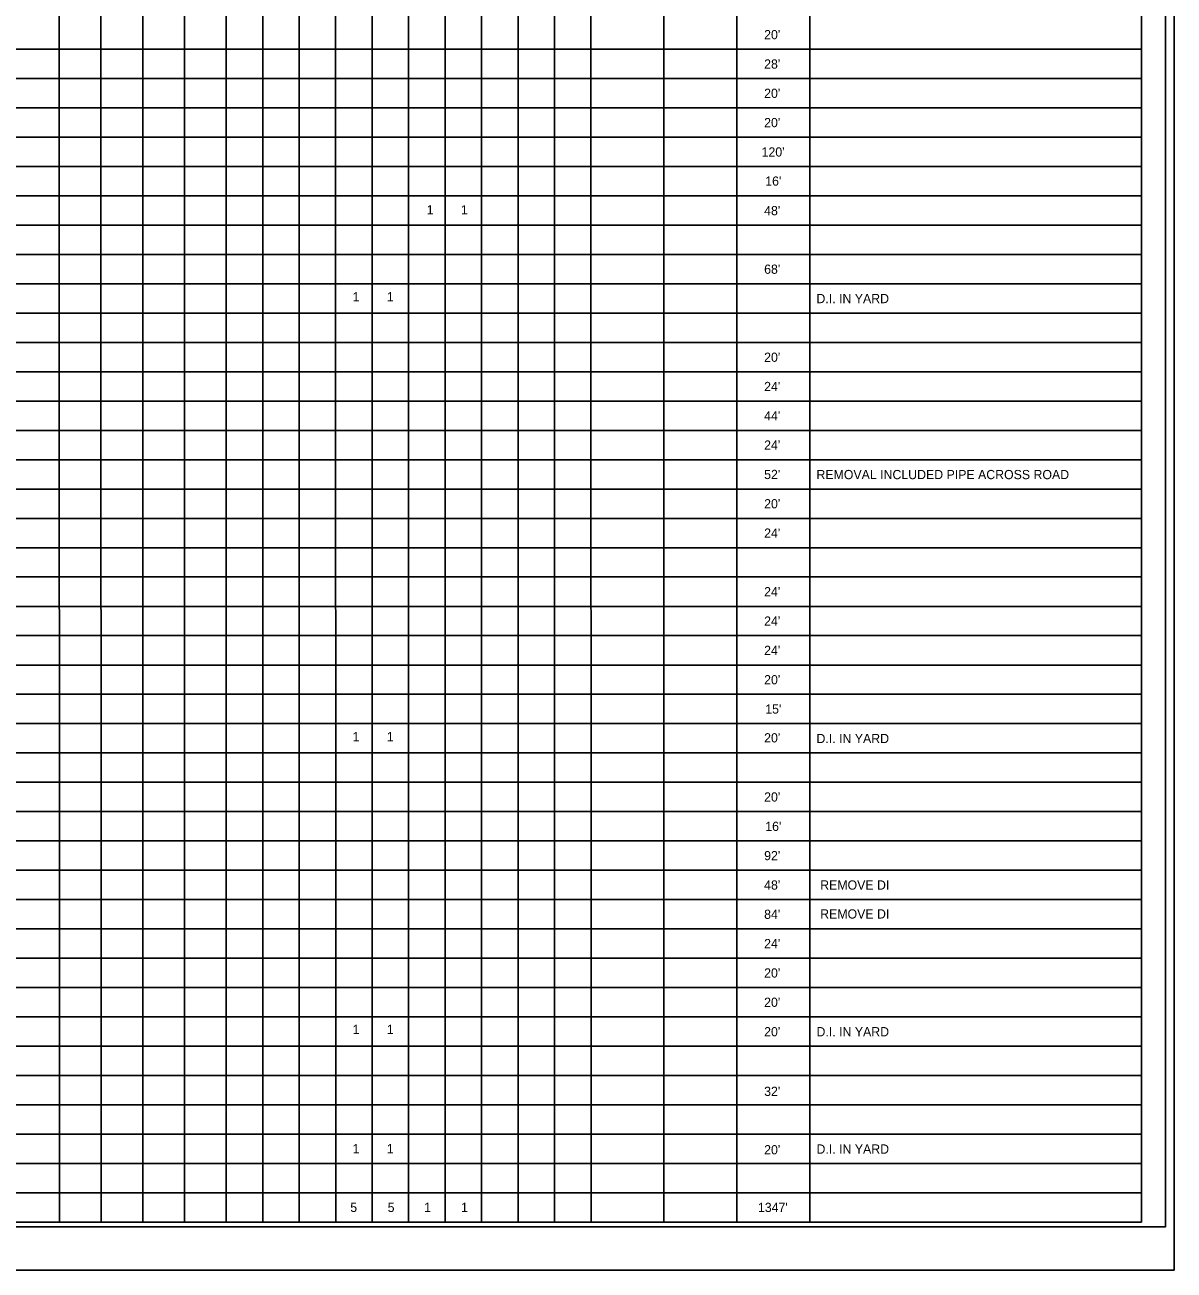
# Model space of a CAD drawing. Extents: x 1912419 to 1914138, y 231793 to 234289.
# Drawn here: x 1913505 to 1914103, y 232988 to 233636 of the extents above; entities that cross this region are included whole.
import ezdxf

# ---------------------------------------------------------------- set-up
doc = ezdxf.new("R2010")
doc.units = 0
for name, color, linetype in [('Sheet Cutting Line CELL', 7, 'Continuous'), ('Sheet Pipe Summary CELL', 7, 'Continuous'), ('Sheet Pipe Summary Grid CELL', 7, 'Continuous'), ('Sheet Plot Border Inside CELL', 7, 'Continuous'), ('Sheet Plot Border Outside CELL', 7, 'Continuous'), ('Sheet Summary Combination CELL', 7, 'Continuous')]:
    doc.layers.add(name, color=color, linetype=linetype)

msp = doc.modelspace()

# ---------------------------------------------------------------- linework, layer by layer
at = {"layer": 'Sheet Cutting Line CELL'}
msp.add_line((1912419.42, 232987.79), (1914103.42, 232987.79), dxfattribs=at)
msp.add_line((1912419.42, 232987.79), (1914103.42, 232987.79), dxfattribs=at)
at = {"layer": 'Sheet Pipe Summary CELL'}
msp.add_lwpolyline([(1914086.42, 234062.79), (1912586.42, 234062.79), (1912586.42, 233012.79), (1914086.42, 233012.79)], close=True, dxfattribs=at)
at = {"layer": 'Sheet Pipe Summary Grid CELL'}
for p, q in [((1913522.74, 233012.85), (1913522.69, 233966.65)), ((1913609.69, 233012.85), (1913609.64, 233966.65)), ((1913647.69, 233012.71), (1913647.64, 233966.66)), ((1913666.69, 233012.71), (1913666.64, 233966.66)), ((1913685.69, 233012.71), (1913685.64, 233966.66)), ((1913704.69, 233012.71), (1913704.64, 233966.66)), ((1913723.69, 233012.71), (1913723.64, 233966.66)), ((1913742.69, 233012.71), (1913742.64, 233966.66)), ((1913761.69, 233012.71), (1913761.64, 233966.66)), ((1913780.69, 233012.71), (1913780.64, 233966.66)), ((1913799.69, 233012.71), (1913799.64, 233966.66)), ((1913799.69, 233012.71), (1913799.64, 233966.66)), ((1913837.69, 233012.72), (1913837.64, 233966.67)), ((1913837.69, 233012.72), (1913837.64, 233966.67)), ((1913875.69, 233012.72), (1913875.64, 233966.67)), ((1913875.69, 233012.72), (1913875.64, 233966.67)), ((1913913.69, 233012.72), (1913913.64, 233966.67)), ((1913913.69, 233012.72), (1913913.64, 233966.67)), ((1913628.69, 233012.71), (1913628.65, 233875.95)), ((1913544.49, 233012.85), (1913544.39, 233790.6)), ((1913566.19, 233012.85), (1913566.14, 233790.6)), ((1913587.94, 233012.85), (1913587.94, 233790.6)), ((1914086.42, 233623.59), (1912586.42, 233623.59)), ((1914086.42, 233608.29), (1912586.42, 233608.29)), ((1914086.42, 233593.04), (1912586.42, 233593.04)), ((1914086.42, 233577.79), (1912586.42, 233577.79)), ((1914086.42, 233562.49), (1912586.42, 233562.49)), ((1914086.42, 233547.24), (1912586.42, 233547.24)), ((1914086.42, 233531.94), (1912586.42, 233531.94)), ((1914086.42, 233516.69), (1912586.42, 233516.69)), ((1914086.42, 233501.44), (1912586.42, 233501.44)), ((1914086.42, 233486.14), (1912586.42, 233486.14)), ((1914086.42, 233470.89), (1912586.42, 233470.89)), ((1914086.42, 233455.59), (1912586.42, 233455.59)), ((1914086.42, 233440.34), (1912586.42, 233440.34)), ((1914086.42, 233425.09), (1912586.42, 233425.09)), ((1914086.42, 233409.79), (1912586.42, 233409.79)), ((1914086.42, 233394.54), (1912586.42, 233394.54)), ((1914086.42, 233379.24), (1912586.42, 233379.24)), ((1914086.42, 233363.99), (1912586.42, 233363.99)), ((1914086.42, 233348.74), (1912586.42, 233348.74)), ((1914086.42, 233333.44), (1912586.42, 233333.44)), ((1914086.42, 233318.19), (1912586.42, 233318.19)), ((1914086.42, 233302.89), (1912586.42, 233302.89)), ((1914086.42, 233287.64), (1912586.42, 233287.64)), ((1914086.42, 233272.39), (1912586.42, 233272.39)), ((1914086.42, 233257.09), (1912586.42, 233257.09)), ((1914086.42, 233241.84), (1912586.42, 233241.84)), ((1914086.42, 233226.54), (1912586.42, 233226.54)), ((1914086.42, 233211.29), (1912586.42, 233211.29)), ((1914086.42, 233196.04), (1912586.42, 233196.04)), ((1914086.42, 233180.74), (1912586.42, 233180.74)), ((1914086.42, 233165.49), (1912586.42, 233165.49)), ((1914086.42, 233150.19), (1912586.42, 233150.19)), ((1914086.42, 233134.94), (1912586.42, 233134.94)), ((1914086.42, 233119.69), (1912586.42, 233119.69)), ((1914086.42, 233104.39), (1912586.42, 233104.39)), ((1914086.42, 233089.14), (1912586.42, 233089.14)), ((1914086.42, 233073.89), (1912586.42, 233073.89)), ((1914086.42, 233073.84), (1912586.42, 233073.84)), ((1914086.42, 233058.59), (1912586.42, 233058.59)), ((1914086.42, 233043.34), (1912586.42, 233043.34)), ((1914086.42, 233028.09), (1912586.42, 233028.09))]:
    msp.add_line(p, q, dxfattribs=at)
at = {"layer": 'Sheet Plot Border Inside CELL'}
msp.add_lwpolyline([(1912432.42, 233010.24), (1914098.92, 233010.24), (1914098.92, 234065.34), (1912432.42, 234065.34)], close=True, dxfattribs=at)
at = {"layer": 'Sheet Plot Border Outside CELL'}
msp.add_lwpolyline([(1912419.42, 232987.79), (1914103.42, 232987.79), (1914103.42, 234087.79), (1912419.42, 234087.79)], close=True, dxfattribs=at)

# ---------------------------------------------------------------- texts
at = {"layer": 'Sheet Summary Combination CELL'}
for s, p in [("20'", (1913889.87, 233628.79)), ("28'", (1913889.87, 233613.49)), ("20'", (1913889.87, 233598.24)), ("20'", (1913889.87, 233582.99)), ("120'", (1913888.55, 233567.69)), ("16'", (1913890.44, 233552.53)), ('1', (1913714.08, 233537.56)), ('1', (1913731.92, 233537.56)), ("48'", (1913889.87, 233537.14)), ("68'", (1913889.87, 233506.64)), ('1', (1913675.5, 233492.28)), ('1', (1913693.34, 233492.28)), ('D.I. IN YARD', (1913917.12, 233491.34)), ("20'", (1913889.87, 233460.79)), ("24'", (1913889.87, 233445.54)), ("44'", (1913889.87, 233430.29)), ("24'", (1913889.87, 233415.04)), ("52'", (1913889.87, 233399.74)), ('REMOVAL INCLUDED PIPE ACROSS ROAD', (1913917.12, 233399.69)), ("20'", (1913889.87, 233384.49)), ("24'", (1913889.87, 233369.19)), ("24'", (1913889.87, 233338.69)), ("24'", (1913889.87, 233323.39)), ("24'", (1913889.87, 233308.14)), ("20'", (1913889.87, 233292.84)), ("15'", (1913890.45, 233277.59)), ('1', (1913675.5, 233263.23)), ('1', (1913693.34, 233263.23)), ("20'", (1913889.87, 233262.58)), ('D.I. IN YARD', (1913917.13, 233262.24)), ("20'", (1913889.87, 233231.79)), ("16'", (1913890.45, 233216.49)), ("92'", (1913889.87, 233201.24)), ("48'", (1913889.87, 233185.94)), ('REMOVE DI', (1913919.06, 233185.94)), ("84'", (1913889.87, 233170.69)), ('REMOVE DI', (1913919.06, 233170.88)), ("24'", (1913889.87, 233155.44)), ("20'", (1913889.87, 233140.14)), ("20'", (1913889.87, 233124.89)), ('1', (1913675.5, 233110.79)), ('1', (1913693.34, 233110.79)), ("20'", (1913889.87, 233109.54)), ('D.I. IN YARD', (1913917.14, 233109.54)), ("32'", (1913889.87, 233078.48)), ('1', (1913675.51, 233048.68)), ('1', (1913693.35, 233048.68)), ("20'", (1913889.87, 233048.07)), ('D.I. IN YARD', (1913917.14, 233048.44)), ('5', (1913674.28, 233018.05)), ('5', (1913693.76, 233018.05)), ('1', (1913712.72, 233018.06)), ('1', (1913731.96, 233018.06)), ("1347'", (1913886.65, 233018.04))]:
    msp.add_text(s, height=4.8, dxfattribs=at).set_placement(p)

doc.saveas('drawing.dxf')
